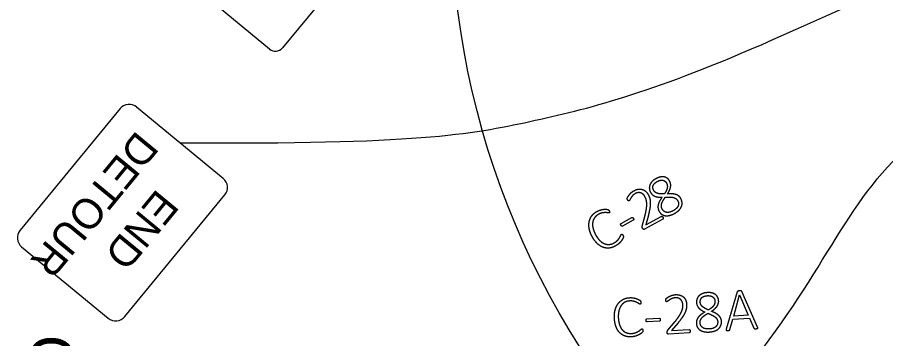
# Model space of a CAD drawing. Extents: x -202 to 1556, y 0 to 676.
# Drawn here: x 54.7 to 150.7, y 70.8 to 106.3 of the extents above; entities that cross this region are included whole.
import ezdxf

# ---------------------------------------------------------------- set-up
doc = ezdxf.new("R2010")
doc.units = 0
for name, color, linetype in [('GM_X_Minor_Lake', 7, 'Continuous'), ('GM_X_Minor_Lake_Text', 7, 'Continuous'), ('GM_X_State_Location', 7, 'Continuous'), ('SH_Data', 7, 'Continuous')]:
    doc.layers.add(name, color=color, linetype=linetype)

msp = doc.modelspace()

# ---------------------------------------------------------------- linework, layer by layer
at = {"layer": 'GM_X_Minor_Lake'}
for p, q in [((93.849, 114.864), (83.995, 102.899)), ((82.588, 102.763), (74.482, 109.437))]:
    msp.add_line(p, q, dxfattribs=at)
for points in [[(66.06, 96.202), (54.999, 82.771)], [(77.462, 88.497), (67.89, 96.379)], [(66.578, 73.235), (77.639, 86.667)], [(55.176, 80.941), (64.748, 73.058)]]:
    msp.add_lwpolyline(points, dxfattribs=at)
for centre, radius, start, end in [((83.223, 103.535), 1, 230.52789, 320.52789), ((67.064, 95.376), 1.3, 50.52789, 140.52789), ((76.636, 87.493), 1.3, 320.52789, 50.52789), ((56.003, 81.944), 1.3, 140.52789, 230.52789), ((65.574, 74.062), 1.3, 230.52789, 320.52789)]:
    msp.add_arc(centre, radius, start, end, dxfattribs=at)
at = {"layer": 'GM_X_State_Location'}
for p, q in [((126.47, 87.965), (126.47, 87.965)), ((127.703, 86.022), (127.703, 86.022)), ((128.045, 86.274), (128.045, 86.274)), ((121.433, 83.51), (122.635, 84.179)), ((122.795, 83.892), (121.593, 83.224)), ((122.798, 84.081), (122.798, 84.081)), ((123.785, 83.215), (124.099, 84.438)), ((126.043, 83.98), (124.039, 82.871)), ((126.061, 84.199), (126.061, 84.199)), ((121.651, 82.203), (121.651, 82.203)), ((134.285, 75.961), (133.06, 71.84)), ((136.534, 72.061), (134.795, 75.994)), ((131.819, 74.933), (131.819, 74.933)), ((124.3, 72.977), (125.672, 73.064)), ((125.693, 72.737), (124.321, 72.649)), ((125.777, 72.906), (125.777, 72.906)), ((126.603, 71.721), (127.411, 72.692)), ((132.12, 72.652), (132.12, 72.652)), ((132.536, 72.736), (132.536, 72.736)), ((123.841, 71.697), (123.841, 71.697)), ((128.972, 71.446), (126.686, 71.3)), ((129.082, 71.636), (129.082, 71.636))]:
    msp.add_line(p, q, dxfattribs=at)
for points in [[(124.458, 84.435), (124.174, 83.352), (125.871, 84.292)], [(133.472, 71.804), (133.793, 72.951), (135.648, 73.069), (136.126, 71.966)], [(127.734, 72.535), (127.014, 71.678), (128.95, 71.801)]]:
    msp.add_lwpolyline(points, dxfattribs=at)
msp.add_lwpolyline([(134.543, 75.621), (135.507, 73.397), (133.889, 73.294), (134.54, 75.62)], close=True, dxfattribs=at)
for points in [[(125.307, 88.469), (125.022, 88.314), (124.851, 88.126)], [(125.809, 88.654), (125.575, 88.614), (125.307, 88.469)], [(126.236, 88.649), (126.044, 88.693), (125.809, 88.654)], [(126.574, 88.486), (126.428, 88.604), (126.236, 88.649)], [(126.811, 88.2), (126.721, 88.367), (126.574, 88.486)], [(124.613, 87.739), (124.546, 87.54), (124.569, 87.34)], [(124.851, 88.126), (124.681, 87.938), (124.613, 87.739)], [(125.039, 87.18), (124.89, 87.454), (124.988, 87.71)], [(124.988, 87.71), (125.086, 87.966), (125.436, 88.156)], [(125.436, 88.156), (125.606, 88.249), (125.762, 88.281)], [(125.762, 88.281), (125.918, 88.314), (126.052, 88.288)], [(126.052, 88.288), (126.186, 88.262), (126.292, 88.18)], [(126.534, 87.421), (126.465, 87.121), (126.221, 86.779)], [(126.292, 88.18), (126.398, 88.098), (126.47, 87.965)], [(126.47, 87.965), (126.603, 87.721), (126.534, 87.421)], [(126.798, 87.169), (126.882, 87.355), (126.913, 87.532)], [(126.92, 87.877), (126.896, 88.045), (126.811, 88.2)], [(126.913, 87.532), (126.944, 87.709), (126.92, 87.877)], [(122.14, 86.34), (122.157, 86.387), (122.209, 86.48)], [(122.209, 86.48), (122.26, 86.572), (122.353, 86.689)], [(122.353, 86.689), (122.445, 86.806), (122.571, 86.923)], [(122.71, 86.583), (122.595, 86.453), (122.522, 86.332)], [(122.571, 86.923), (122.697, 87.04), (122.855, 87.127)], [(123.006, 86.813), (122.825, 86.713), (122.71, 86.583)], [(122.855, 87.127), (123.115, 87.271), (123.352, 87.301)], [(123.33, 86.919), (123.172, 86.904), (123.006, 86.813)], [(123.626, 86.888), (123.488, 86.934), (123.33, 86.919)], [(123.352, 87.301), (123.588, 87.33), (123.79, 87.27)], [(123.876, 86.742), (123.763, 86.843), (123.626, 86.888)], [(123.79, 87.27), (123.991, 87.209), (124.15, 87.071)], [(124.066, 86.505), (123.99, 86.642), (123.876, 86.742)], [(124.201, 86.197), (124.142, 86.367), (124.066, 86.505)], [(124.15, 87.071), (124.31, 86.932), (124.416, 86.74)], [(124.416, 86.74), (124.514, 86.562), (124.582, 86.369)], [(124.569, 87.34), (124.592, 87.14), (124.69, 86.959)], [(124.69, 86.959), (124.773, 86.806), (124.895, 86.699)], [(124.895, 86.699), (125.017, 86.591), (125.177, 86.526)], [(125.208, 86.975), (125.106, 87.057), (125.039, 87.18)], [(125.177, 86.526), (125.338, 86.46), (125.537, 86.434)], [(125.454, 86.845), (125.311, 86.892), (125.208, 86.975)], [(125.787, 86.784), (125.597, 86.798), (125.454, 86.845)], [(125.537, 86.434), (125.736, 86.408), (125.973, 86.417)], [(125.973, 86.417), (125.818, 86.202), (125.708, 86.002)], [(126.221, 86.779), (125.976, 86.769), (125.787, 86.784)], [(126.078, 86.032), (126.181, 86.213), (126.334, 86.426)], [(126.334, 86.426), (126.614, 86.441), (126.833, 86.435)], [(126.582, 86.789), (126.714, 86.984), (126.798, 87.169)], [(127.092, 86.788), (126.861, 86.803), (126.582, 86.789)], [(126.833, 86.435), (127.053, 86.429), (127.219, 86.387)], [(127.504, 86.713), (127.322, 86.773), (127.092, 86.788)], [(127.219, 86.387), (127.386, 86.345), (127.505, 86.257)], [(127.82, 86.547), (127.685, 86.653), (127.504, 86.713)], [(128.045, 86.274), (127.954, 86.441), (127.82, 86.547)], [(122.123, 86.27), (122.123, 86.293), (122.14, 86.34)], [(122.127, 86.226), (122.122, 86.248), (122.123, 86.27)], [(122.141, 86.179), (122.132, 86.204), (122.127, 86.226)], [(122.17, 86.12), (122.151, 86.155), (122.141, 86.179)], [(122.211, 86.056), (122.191, 86.083), (122.17, 86.12)], [(122.252, 86.017), (122.232, 86.03), (122.211, 86.056)], [(122.291, 86.003), (122.272, 86.004), (122.252, 86.017)], [(122.328, 86.012), (122.31, 86.002), (122.291, 86.003)], [(122.406, 86.121), (122.362, 86.031), (122.328, 86.012)], [(122.522, 86.332), (122.449, 86.211), (122.406, 86.121)], [(124.275, 85.788), (124.259, 86.027), (124.201, 86.197)], [(124.254, 85.222), (124.292, 85.55), (124.275, 85.788)], [(124.582, 86.369), (124.65, 86.176), (124.666, 85.913)], [(124.666, 85.913), (124.683, 85.65), (124.635, 85.294)], [(125.55, 85.613), (125.502, 85.422), (125.521, 85.237)], [(125.708, 86.002), (125.598, 85.803), (125.55, 85.613)], [(125.898, 85.392), (125.886, 85.534), (125.93, 85.693)], [(125.93, 85.693), (125.975, 85.851), (126.078, 86.032)], [(127.741, 85.441), (127.619, 85.153), (127.204, 84.927)], [(127.505, 86.257), (127.623, 86.169), (127.703, 86.022)], [(127.703, 86.022), (127.863, 85.729), (127.741, 85.441)], [(128.187, 85.808), (128.173, 86.037), (128.045, 86.274)], [(128.11, 85.367), (128.202, 85.579), (128.187, 85.808)], [(118.196, 84.351), (118.412, 84.646), (118.765, 84.842)], [(118.924, 84.514), (118.664, 84.369), (118.504, 84.143)], [(118.765, 84.842), (118.931, 84.934), (119.104, 84.989)], [(119.367, 84.683), (119.162, 84.646), (118.924, 84.514)], [(119.104, 84.989), (119.278, 85.045), (119.437, 85.069)], [(119.73, 84.715), (119.571, 84.72), (119.367, 84.683)], [(119.437, 85.069), (119.596, 85.094), (119.735, 85.089)], [(119.994, 84.691), (119.888, 84.709), (119.73, 84.715)], [(119.735, 85.089), (119.875, 85.084), (119.935, 85.067)], [(119.935, 85.067), (119.995, 85.05), (120.015, 85.039)], [(120.14, 84.696), (120.1, 84.673), (119.994, 84.691)], [(120.015, 85.039), (120.034, 85.027), (120.052, 85.009)], [(120.052, 85.009), (120.07, 84.99), (120.088, 84.965)], [(120.088, 84.965), (120.106, 84.939), (120.125, 84.905)], [(120.125, 84.905), (120.147, 84.865), (120.16, 84.832)], [(120.168, 84.726), (120.16, 84.707), (120.14, 84.696)], [(120.16, 84.832), (120.172, 84.8), (120.174, 84.773)], [(120.174, 84.773), (120.176, 84.746), (120.168, 84.726)], [(124.099, 84.438), (124.217, 84.894), (124.254, 85.222)], [(124.635, 85.294), (124.587, 84.937), (124.458, 84.435)], [(125.521, 85.237), (125.539, 85.051), (125.64, 84.867)], [(125.64, 84.867), (125.759, 84.648), (125.935, 84.525)], [(125.986, 85.108), (125.91, 85.249), (125.898, 85.392)], [(125.935, 84.525), (126.112, 84.403), (126.331, 84.373)], [(126.464, 84.747), (126.154, 84.8), (125.986, 85.108)], [(127.204, 84.927), (126.775, 84.694), (126.464, 84.747)], [(126.805, 84.405), (127.059, 84.466), (127.333, 84.615)], [(127.333, 84.615), (127.627, 84.775), (127.822, 84.965)], [(127.822, 84.965), (128.018, 85.155), (128.11, 85.367)], [(117.929, 82.9), (117.843, 83.323), (117.911, 83.689)], [(117.911, 83.689), (117.979, 84.056), (118.196, 84.351)], [(118.302, 83.627), (118.259, 83.337), (118.337, 82.99)], [(118.504, 84.143), (118.345, 83.917), (118.302, 83.627)], [(121.389, 83.445), (121.396, 83.49), (121.433, 83.51)], [(122.635, 84.179), (122.652, 84.188), (122.672, 84.19)], [(122.672, 84.19), (122.692, 84.191), (122.713, 84.181)], [(122.713, 84.181), (122.734, 84.17), (122.755, 84.146)], [(122.755, 84.146), (122.776, 84.122), (122.798, 84.081)], [(122.838, 83.955), (122.832, 83.913), (122.795, 83.892)], [(122.798, 84.081), (122.844, 83.998), (122.838, 83.955)], [(125.871, 84.292), (125.894, 84.305), (125.919, 84.306)], [(125.919, 84.306), (125.945, 84.307), (125.97, 84.295)], [(125.97, 84.295), (125.996, 84.283), (126.019, 84.258)], [(126.019, 84.258), (126.042, 84.233), (126.061, 84.199)], [(126.083, 84.017), (126.069, 83.995), (126.043, 83.98)], [(126.061, 84.199), (126.08, 84.165), (126.089, 84.131)], [(126.098, 84.068), (126.097, 84.04), (126.083, 84.017)], [(126.089, 84.131), (126.099, 84.097), (126.098, 84.068)], [(126.331, 84.373), (126.551, 84.343), (126.805, 84.405)], [(118.266, 82.023), (118.014, 82.476), (117.929, 82.9)], [(118.337, 82.99), (118.416, 82.644), (118.631, 82.257)], [(121.427, 83.319), (121.383, 83.4), (121.389, 83.445)], [(121.514, 83.221), (121.472, 83.239), (121.427, 83.319)], [(121.593, 83.224), (121.556, 83.203), (121.514, 83.221)], [(123.774, 83.146), (123.776, 83.177), (123.785, 83.215)], [(123.777, 83.088), (123.773, 83.115), (123.774, 83.146)], [(123.794, 83.03), (123.781, 83.06), (123.777, 83.088)], [(123.827, 82.963), (123.807, 83), (123.794, 83.03)], [(123.877, 82.893), (123.851, 82.92), (123.827, 82.963)], [(123.931, 82.857), (123.903, 82.866), (123.877, 82.893)], [(123.986, 82.852), (123.958, 82.848), (123.931, 82.857)], [(124.039, 82.871), (124.014, 82.856), (123.986, 82.852)], [(118.811, 81.298), (118.512, 81.582), (118.266, 82.023)], [(118.631, 82.257), (118.837, 81.887), (119.076, 81.646)], [(119.076, 81.646), (119.316, 81.404), (119.577, 81.292)], [(120.683, 81.38), (120.915, 81.51), (121.056, 81.665)], [(121.056, 81.665), (121.196, 81.82), (121.28, 81.96)], [(121.28, 81.96), (121.363, 82.1), (121.409, 82.202)], [(121.409, 82.202), (121.456, 82.305), (121.499, 82.329)], [(121.62, 81.827), (121.563, 81.715), (121.457, 81.577)], [(121.499, 82.329), (121.516, 82.338), (121.531, 82.338)], [(121.531, 82.338), (121.547, 82.337), (121.564, 82.322)], [(121.564, 82.322), (121.582, 82.308), (121.604, 82.278)], [(121.604, 82.278), (121.625, 82.249), (121.651, 82.203)], [(121.689, 81.983), (121.677, 81.94), (121.62, 81.827)], [(121.651, 82.203), (121.668, 82.172), (121.68, 82.144)], [(121.68, 82.144), (121.691, 82.117), (121.697, 82.094)], [(121.702, 82.048), (121.701, 82.025), (121.689, 81.983)], [(121.697, 82.094), (121.702, 82.071), (121.702, 82.048)], [(119.439, 80.889), (119.11, 81.014), (118.811, 81.298)], [(120.121, 80.801), (119.769, 80.765), (119.439, 80.889)], [(119.577, 81.292), (119.838, 81.18), (120.119, 81.201)], [(120.119, 81.201), (120.4, 81.223), (120.683, 81.38)], [(120.821, 81.032), (120.472, 80.837), (120.121, 80.801)], [(121.195, 81.296), (121.039, 81.153), (120.821, 81.032)], [(121.457, 81.577), (121.352, 81.44), (121.195, 81.296)], [(130.975, 75.879), (130.651, 75.858), (130.418, 75.76)], [(131.509, 75.836), (131.28, 75.898), (130.975, 75.879)], [(131.894, 75.652), (131.738, 75.773), (131.509, 75.836)], [(134.311, 76.007), (134.293, 75.988), (134.285, 75.961)], [(134.36, 76.038), (134.33, 76.027), (134.311, 76.007)], [(134.435, 76.058), (134.391, 76.05), (134.36, 76.038)], [(134.534, 76.069), (134.479, 76.066), (134.435, 76.058)], [(134.638, 76.071), (134.593, 76.073), (134.534, 76.069)], [(134.714, 76.061), (134.682, 76.069), (134.638, 76.071)], [(134.765, 76.036), (134.745, 76.053), (134.714, 76.061)], [(134.795, 75.994), (134.784, 76.019), (134.765, 76.036)], [(121.104, 74.646), (121.323, 74.948), (121.645, 75.121)], [(121.645, 75.121), (121.967, 75.294), (122.37, 75.32)], [(122.373, 74.955), (122.075, 74.936), (121.834, 74.801)], [(122.37, 75.32), (122.559, 75.332), (122.74, 75.307)], [(122.845, 74.918), (122.644, 74.973), (122.373, 74.955)], [(122.74, 75.307), (122.92, 75.283), (123.074, 75.237)], [(123.186, 74.791), (123.045, 74.864), (122.845, 74.918)], [(123.074, 75.237), (123.228, 75.191), (123.352, 75.126)], [(123.352, 75.126), (123.476, 75.062), (123.523, 75.021)], [(123.523, 75.021), (123.57, 74.979), (123.583, 74.96)], [(123.583, 74.96), (123.595, 74.942), (123.604, 74.917)], [(123.604, 74.917), (123.612, 74.893), (123.617, 74.862)], [(126.388, 75.037), (126.385, 75.076), (126.387, 75.103)], [(126.387, 75.103), (126.388, 75.129), (126.394, 75.151)], [(126.397, 74.962), (126.39, 74.994), (126.388, 75.037)], [(126.394, 75.151), (126.399, 75.173), (126.409, 75.193)], [(126.417, 74.909), (126.404, 74.929), (126.397, 74.962)], [(126.409, 75.193), (126.419, 75.214), (126.455, 75.249)], [(126.447, 74.879), (126.43, 74.888), (126.417, 74.909)], [(126.483, 74.872), (126.464, 74.871), (126.447, 74.879)], [(126.455, 75.249), (126.49, 75.284), (126.576, 75.346)], [(126.6, 74.937), (126.523, 74.874), (126.483, 74.872)], [(126.576, 75.346), (126.663, 75.407), (126.796, 75.473)], [(126.796, 75.078), (126.678, 75), (126.6, 74.937)], [(126.796, 75.473), (126.93, 75.539), (127.094, 75.591)], [(127.074, 75.224), (126.914, 75.157), (126.796, 75.078)], [(127.439, 75.305), (127.233, 75.292), (127.074, 75.224)], [(127.094, 75.591), (127.258, 75.643), (127.437, 75.654)], [(127.437, 75.654), (127.734, 75.673), (127.96, 75.599)], [(127.778, 75.263), (127.628, 75.317), (127.439, 75.305)], [(128.032, 75.108), (127.927, 75.208), (127.778, 75.263)], [(127.96, 75.599), (128.187, 75.524), (128.343, 75.383)], [(128.196, 74.869), (128.136, 75.008), (128.032, 75.108)], [(128.265, 74.574), (128.255, 74.73), (128.196, 74.869)], [(128.343, 75.383), (128.5, 75.242), (128.584, 75.049)], [(128.584, 75.049), (128.668, 74.855), (128.682, 74.636)], [(129.831, 75.166), (129.767, 74.975), (129.781, 74.768)], [(130.039, 75.509), (129.894, 75.357), (129.831, 75.166)], [(130.418, 75.76), (130.184, 75.661), (130.039, 75.509)], [(130.19, 74.823), (130.17, 75.133), (130.367, 75.325)], [(130.367, 75.325), (130.564, 75.516), (130.961, 75.541)], [(130.961, 75.541), (131.154, 75.554), (131.309, 75.518)], [(131.309, 75.518), (131.465, 75.481), (131.575, 75.402)], [(131.575, 75.402), (131.686, 75.322), (131.747, 75.203)], [(131.819, 74.933), (131.837, 74.655), (131.648, 74.412)], [(131.747, 75.203), (131.809, 75.083), (131.819, 74.933)], [(132.132, 75.361), (132.049, 75.53), (131.894, 75.652)], [(132.227, 75.003), (132.215, 75.193), (132.132, 75.361)], [(132.19, 74.664), (132.239, 74.826), (132.227, 75.003)], [(120.708, 72.989), (120.675, 73.507), (120.78, 73.926)], [(120.78, 73.926), (120.885, 74.345), (121.104, 74.646)], [(121.43, 74.422), (121.266, 74.179), (121.188, 73.832)], [(121.834, 74.801), (121.593, 74.666), (121.43, 74.422)], [(123.415, 74.656), (123.327, 74.718), (123.186, 74.791)], [(123.548, 74.597), (123.503, 74.594), (123.415, 74.656)], [(123.587, 74.613), (123.571, 74.599), (123.548, 74.597)], [(123.612, 74.652), (123.602, 74.627), (123.587, 74.613)], [(123.625, 74.712), (123.622, 74.677), (123.612, 74.652)], [(123.617, 74.862), (123.622, 74.832), (123.625, 74.792)], [(123.625, 74.792), (123.628, 74.747), (123.625, 74.712)], [(128.148, 73.836), (128.236, 74.059), (128.256, 74.238)], [(128.256, 74.238), (128.275, 74.416), (128.265, 74.574)], [(128.674, 74.23), (128.652, 74.026), (128.555, 73.782)], [(128.682, 74.636), (128.695, 74.433), (128.674, 74.23)], [(129.781, 74.768), (129.792, 74.595), (129.857, 74.447)], [(129.857, 74.447), (129.922, 74.298), (130.04, 74.171)], [(130.04, 74.171), (130.159, 74.044), (130.328, 73.936)], [(130.258, 74.565), (130.199, 74.683), (130.19, 74.823)], [(130.426, 74.344), (130.316, 74.447), (130.258, 74.565)], [(130.328, 73.936), (130.498, 73.829), (130.717, 73.738)], [(130.702, 74.149), (130.536, 74.242), (130.426, 74.344)], [(131.094, 73.962), (130.867, 74.056), (130.702, 74.149)], [(131.648, 74.412), (131.459, 74.169), (131.094, 73.962)], [(131.425, 73.819), (131.628, 73.94), (131.782, 74.073)], [(131.782, 74.073), (131.936, 74.206), (132.039, 74.354)], [(132.039, 74.354), (132.141, 74.501), (132.19, 74.664)], [(120.888, 72.1), (120.74, 72.485), (120.708, 72.989)], [(121.188, 73.832), (121.11, 73.486), (121.138, 73.044)], [(121.138, 73.044), (121.165, 72.622), (121.277, 72.3)], [(124.232, 72.936), (124.257, 72.974), (124.3, 72.977)], [(125.672, 73.064), (125.692, 73.065), (125.71, 73.058)], [(125.71, 73.058), (125.729, 73.051), (125.743, 73.033)], [(125.743, 73.033), (125.757, 73.014), (125.766, 72.983)], [(125.766, 72.983), (125.774, 72.952), (125.777, 72.906)], [(127.411, 72.692), (127.713, 73.053), (127.887, 73.333)], [(128.261, 73.236), (128.066, 72.934), (127.734, 72.535)], [(127.887, 73.333), (128.061, 73.614), (128.148, 73.836)], [(128.555, 73.782), (128.457, 73.537), (128.261, 73.236)], [(129.995, 73.186), (129.871, 73.033), (129.81, 72.857)], [(130.302, 73.473), (130.118, 73.338), (129.995, 73.186)], [(130.217, 72.839), (130.266, 72.974), (130.373, 73.099)], [(130.717, 73.738), (130.485, 73.608), (130.302, 73.473)], [(130.373, 73.099), (130.48, 73.223), (130.65, 73.344)], [(130.65, 73.344), (130.82, 73.465), (131.048, 73.594)], [(131.048, 73.594), (131.308, 73.489), (131.505, 73.392)], [(131.888, 73.603), (131.685, 73.714), (131.425, 73.819)], [(131.505, 73.392), (131.702, 73.295), (131.835, 73.186)], [(131.835, 73.186), (131.968, 73.078), (132.039, 72.948)], [(132.23, 73.362), (132.09, 73.493), (131.888, 73.603)], [(132.039, 72.948), (132.11, 72.818), (132.12, 72.652)], [(132.447, 73.079), (132.37, 73.232), (132.23, 73.362)], [(132.536, 72.736), (132.524, 72.926), (132.447, 73.079)], [(121.28, 71.461), (121.036, 71.715), (120.888, 72.1)], [(121.277, 72.3), (121.389, 71.979), (121.577, 71.766)], [(124.212, 72.807), (124.206, 72.899), (124.232, 72.936)], [(124.248, 72.681), (124.218, 72.715), (124.212, 72.807)], [(124.321, 72.649), (124.278, 72.647), (124.248, 72.681)], [(125.759, 72.775), (125.735, 72.739), (125.693, 72.737)], [(125.777, 72.906), (125.783, 72.811), (125.759, 72.775)], [(129.81, 72.857), (129.749, 72.681), (129.762, 72.471)], [(129.762, 72.471), (129.778, 72.223), (129.887, 72.037)], [(129.887, 72.037), (129.996, 71.852), (130.182, 71.732)], [(130.179, 72.545), (130.168, 72.705), (130.217, 72.839)], [(130.46, 72.016), (130.201, 72.195), (130.179, 72.545)], [(131.207, 71.868), (130.72, 71.837), (130.46, 72.016)], [(131.91, 72.108), (131.679, 71.898), (131.207, 71.868)], [(132.12, 72.652), (132.141, 72.318), (131.91, 72.108)], [(132.214, 71.886), (132.386, 72.04), (132.47, 72.254)], [(132.47, 72.254), (132.553, 72.468), (132.536, 72.736)], [(136.557, 71.982), (136.556, 72.013), (136.534, 72.061)], [(121.857, 71.089), (121.524, 71.207), (121.28, 71.461)], [(121.577, 71.766), (121.765, 71.553), (122.027, 71.451)], [(122.589, 70.996), (122.19, 70.97), (121.857, 71.089)], [(122.027, 71.451), (122.29, 71.35), (122.614, 71.37)], [(123.04, 71.074), (122.837, 71.012), (122.589, 70.996)], [(122.614, 71.37), (122.879, 71.387), (123.073, 71.467)], [(123.398, 71.215), (123.243, 71.136), (123.04, 71.074)], [(123.073, 71.467), (123.266, 71.546), (123.402, 71.637)], [(123.652, 71.371), (123.552, 71.294), (123.398, 71.215)], [(123.402, 71.637), (123.537, 71.727), (123.623, 71.8)], [(123.623, 71.8), (123.709, 71.873), (123.758, 71.876)], [(123.781, 71.481), (123.752, 71.448), (123.652, 71.371)], [(123.758, 71.876), (123.777, 71.877), (123.791, 71.87)], [(123.821, 71.535), (123.81, 71.514), (123.781, 71.481)], [(123.791, 71.87), (123.805, 71.863), (123.814, 71.842)], [(123.814, 71.842), (123.824, 71.821), (123.831, 71.785)], [(123.836, 71.579), (123.831, 71.555), (123.821, 71.535)], [(123.831, 71.785), (123.838, 71.75), (123.841, 71.697)], [(123.842, 71.632), (123.841, 71.602), (123.836, 71.579)], [(123.841, 71.697), (123.844, 71.661), (123.842, 71.632)], [(126.532, 71.549), (126.534, 71.582), (126.542, 71.609)], [(126.534, 71.474), (126.531, 71.517), (126.532, 71.549)], [(126.549, 71.39), (126.537, 71.425), (126.534, 71.474)], [(126.542, 71.609), (126.55, 71.636), (126.565, 71.663)], [(126.582, 71.335), (126.561, 71.355), (126.549, 71.39)], [(126.565, 71.663), (126.579, 71.69), (126.603, 71.721)], [(126.63, 71.307), (126.603, 71.315), (126.582, 71.335)], [(126.686, 71.3), (126.657, 71.298), (126.63, 71.307)], [(128.95, 71.801), (128.976, 71.803), (128.999, 71.793)], [(129.024, 71.462), (129.002, 71.447), (128.972, 71.446)], [(128.999, 71.793), (129.023, 71.783), (129.041, 71.761)], [(129.059, 71.502), (129.046, 71.476), (129.024, 71.462)], [(129.041, 71.761), (129.059, 71.739), (129.069, 71.707)], [(129.078, 71.562), (129.072, 71.527), (129.059, 71.502)], [(129.069, 71.707), (129.079, 71.675), (129.082, 71.636)], [(129.082, 71.636), (129.084, 71.597), (129.078, 71.562)], [(130.182, 71.732), (130.369, 71.613), (130.625, 71.562)], [(130.625, 71.562), (130.882, 71.511), (131.193, 71.531)], [(131.193, 71.531), (131.527, 71.552), (131.784, 71.642)], [(131.784, 71.642), (132.041, 71.732), (132.214, 71.886)], [(133.06, 71.84), (133.044, 71.789), (133.047, 71.76)], [(133.047, 71.76), (133.051, 71.731), (133.073, 71.716)], [(133.073, 71.716), (133.095, 71.701), (133.141, 71.697)], [(133.141, 71.697), (133.187, 71.693), (133.256, 71.698)], [(133.256, 71.698), (133.318, 71.702), (133.358, 71.711)], [(133.358, 71.711), (133.399, 71.72), (133.421, 71.733)], [(133.421, 71.733), (133.443, 71.746), (133.455, 71.763)], [(133.455, 71.763), (133.467, 71.78), (133.472, 71.804)], [(136.126, 71.966), (136.138, 71.943), (136.15, 71.928)], [(136.15, 71.928), (136.163, 71.912), (136.186, 71.904)], [(136.186, 71.904), (136.21, 71.895), (136.251, 71.893)], [(136.251, 71.893), (136.292, 71.891), (136.361, 71.895)], [(136.361, 71.895), (136.429, 71.9), (136.473, 71.907)], [(136.473, 71.907), (136.517, 71.915), (136.537, 71.933)], [(136.537, 71.933), (136.557, 71.95), (136.557, 71.982)]]:
    msp.add_open_spline(points, degree=2, dxfattribs=at)
at = {"layer": 'SH_Data'}
msp.add_circle((192.681, 118.45), 90, dxfattribs=at)
for points in [[(72.676, 92.438), (98.675, 92.219), (111.174, 94.546), (130.998, 99.432), (168.349, 118.148), (182.667, 118.561)], [(99.584, 38.494), (114.011, 45.821), (142.225, 70.89), (149.271, 95.631), (176.178, 102.836), (190.467, 101.824)]]:
    msp.add_open_spline(points, degree=3, dxfattribs=at)

# ---------------------------------------------------------------- texts
at = {"layer": 'GM_X_Minor_Lake'}
for s, p in [('DETOUR', (67.924, 93.891)), ('END', (70.169, 87.458))]:
    msp.add_text(s, height=3.3333, rotation=230.52789, dxfattribs=at).set_placement(p)
at = {"layer": 'GM_X_Minor_Lake_Text'}
msp.add_text('ROAD CLOSED', height=5, rotation=90.36941, dxfattribs=at).set_placement((61.293, 22.554))

doc.saveas('drawing.dxf')
